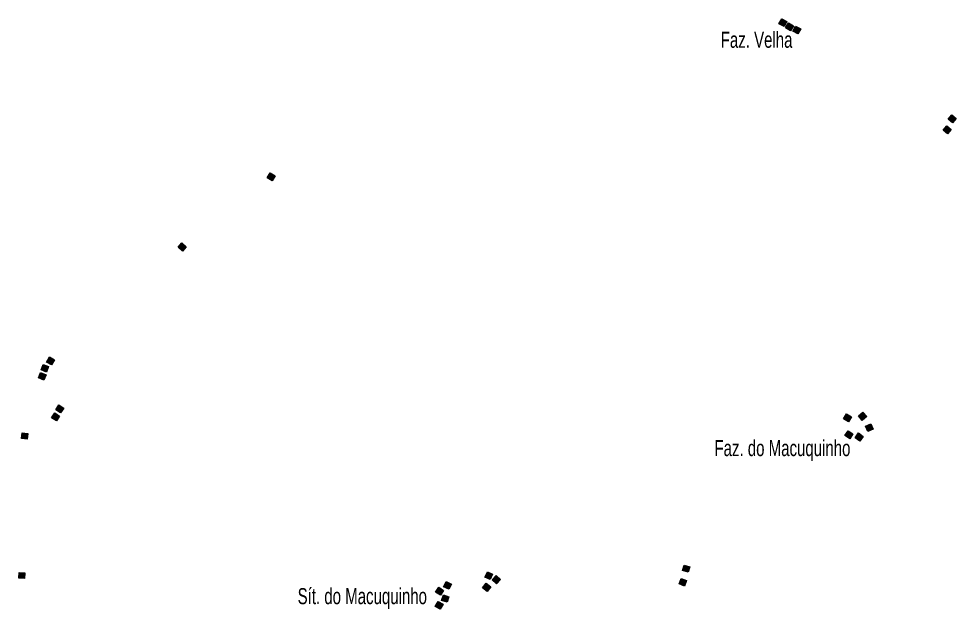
# Model space of a CAD drawing. Extents: x 679 to 705, y 7427.4 to 7455.4.
# Drawn here: x 688.118 to 692.796, y 7447.742 to 7450.688 of the extents above; entities that cross this region are included whole.
import ezdxf

# ---------------------------------------------------------------- set-up
doc = ezdxf.new("R2010")
doc.units = 0
doc.header["$LTSCALE"] = 0.032
doc.layers.add('2', color=7, linetype='Continuous', lineweight=25)
doc.layers.add('61', color=7, linetype='Continuous')

msp = doc.modelspace()

# ---------------------------------------------------------------- hatches: boundary and pattern name
at = {"layer": '2'}
for points in [[(691.9249, 7450.6883), (691.9505, 7450.6747), (691.937, 7450.6491), (691.9113, 7450.6627)], [(691.9831, 7450.6532), (691.9681, 7450.6284), (691.9433, 7450.6434), (691.9583, 7450.6682)], [(692.0196, 7450.6379), (692.0055, 7450.6126), (691.9801, 7450.6267), (691.9943, 7450.6521)], [(692.7735, 7450.2092), (692.7957, 7450.1905), (692.777, 7450.1683), (692.7548, 7450.187)], [(692.7708, 7450.1361), (692.7522, 7450.1138), (692.7299, 7450.1324), (692.7485, 7450.1547)], [(689.3721, 7449.9198), (689.3972, 7449.9053), (689.3827, 7449.8802), (689.3575, 7449.8947)], [(688.9321, 7449.5697), (688.9539, 7449.5507), (688.9349, 7449.5288), (688.913, 7449.5479)], [(688.2394, 7448.9629), (688.2665, 7448.9527), (688.2563, 7448.9256), (688.2292, 7448.9358)], [(688.271, 7449.0007), (688.2962, 7448.9863), (688.2817, 7448.9611), (688.2566, 7448.9756)], [(688.2272, 7448.9233), (688.254, 7448.9122), (688.2429, 7448.8854), (688.2161, 7448.8965)], [(688.3185, 7448.7617), (688.3426, 7448.7456), (688.3266, 7448.7215), (688.3024, 7448.7376)], [(692.3303, 7448.7253), (692.349, 7448.7031), (692.3268, 7448.6844), (692.3082, 7448.7066)], [(688.2973, 7448.7217), (688.3218, 7448.7062), (688.3063, 7448.6817), (688.2818, 7448.6972)], [(692.2474, 7448.7167), (692.2723, 7448.7018), (692.2575, 7448.6769), (692.2326, 7448.6918)], [(692.2561, 7448.6325), (692.2804, 7448.6166), (692.2646, 7448.5923), (692.2403, 7448.6082)], [(692.3688, 7448.667), (692.3811, 7448.6407), (692.3548, 7448.6284), (692.3425, 7448.6547)], [(688.1637, 7448.6196), (688.1606, 7448.5907), (688.1318, 7448.5938), (688.1349, 7448.6226)], [(692.3082, 7448.6215), (692.3316, 7448.6043), (692.3144, 7448.581), (692.2911, 7448.5981)], [(690.4825, 7447.9163), (690.4699, 7447.8902), (690.4438, 7447.9027), (690.4564, 7447.9289)], [(691.4663, 7447.9538), (691.4574, 7447.9262), (691.4298, 7447.9351), (691.4387, 7447.9627)], [(688.1485, 7447.9244), (688.147, 7447.8954), (688.118, 7447.897), (688.1195, 7447.9259)], [(690.5004, 7447.9099), (690.5212, 7447.8897), (690.5011, 7447.8688), (690.4802, 7447.889)], [(691.4236, 7447.8954), (691.4506, 7447.8848), (691.44, 7447.8578), (691.413, 7447.8684)], [(690.2376, 7447.8359), (690.222, 7447.8115), (690.1976, 7447.8271), (690.2132, 7447.8515)], [(690.2499, 7447.8798), (690.2764, 7447.8678), (690.2644, 7447.8414), (690.238, 7447.8534)], [(690.4509, 7447.8714), (690.4734, 7447.8531), (690.4551, 7447.8306), (690.4326, 7447.8489)], [(690.2372, 7447.8137), (690.2646, 7447.8041), (690.255, 7447.7767), (690.2276, 7447.7863)], [(690.2099, 7447.7814), (690.2353, 7447.7674), (690.2213, 7447.742), (690.1959, 7447.756)]]:
    msp.add_hatch(color=256, dxfattribs=at).paths.add_polyline_path(points)

# ---------------------------------------------------------------- linework, layer by layer
for points in [[(691.9249, 7450.6883), (691.9505, 7450.6747), (691.937, 7450.6491), (691.9113, 7450.6627)], [(691.9831, 7450.6532), (691.9681, 7450.6284), (691.9433, 7450.6434), (691.9583, 7450.6682)], [(692.0196, 7450.6379), (692.0055, 7450.6126), (691.9801, 7450.6267), (691.9943, 7450.6521)], [(692.7735, 7450.2092), (692.7957, 7450.1905), (692.777, 7450.1683), (692.7548, 7450.187)], [(692.7708, 7450.1361), (692.7522, 7450.1138), (692.7299, 7450.1324), (692.7485, 7450.1547)], [(689.3721, 7449.9198), (689.3972, 7449.9053), (689.3827, 7449.8802), (689.3575, 7449.8947)], [(688.9321, 7449.5697), (688.9539, 7449.5507), (688.9349, 7449.5288), (688.913, 7449.5479)], [(688.2394, 7448.9629), (688.2665, 7448.9527), (688.2563, 7448.9256), (688.2292, 7448.9358)], [(688.271, 7449.0007), (688.2962, 7448.9863), (688.2817, 7448.9611), (688.2566, 7448.9756)], [(688.2272, 7448.9233), (688.254, 7448.9122), (688.2429, 7448.8854), (688.2161, 7448.8965)], [(688.3185, 7448.7617), (688.3426, 7448.7456), (688.3266, 7448.7215), (688.3024, 7448.7376)], [(692.3303, 7448.7253), (692.349, 7448.7031), (692.3268, 7448.6844), (692.3082, 7448.7066)], [(688.2973, 7448.7217), (688.3218, 7448.7062), (688.3063, 7448.6817), (688.2818, 7448.6972)], [(692.2474, 7448.7167), (692.2723, 7448.7018), (692.2575, 7448.6769), (692.2326, 7448.6918)], [(692.2561, 7448.6325), (692.2804, 7448.6166), (692.2646, 7448.5923), (692.2403, 7448.6082)], [(692.3688, 7448.667), (692.3811, 7448.6407), (692.3548, 7448.6284), (692.3425, 7448.6547)], [(688.1637, 7448.6196), (688.1606, 7448.5907), (688.1318, 7448.5938), (688.1349, 7448.6226)], [(692.3082, 7448.6215), (692.3316, 7448.6043), (692.3144, 7448.581), (692.2911, 7448.5981)], [(690.4825, 7447.9163), (690.4699, 7447.8902), (690.4438, 7447.9027), (690.4564, 7447.9289)], [(691.4663, 7447.9538), (691.4574, 7447.9262), (691.4298, 7447.9351), (691.4387, 7447.9627)], [(688.1485, 7447.9244), (688.147, 7447.8954), (688.118, 7447.897), (688.1195, 7447.9259)], [(690.5004, 7447.9099), (690.5212, 7447.8897), (690.5011, 7447.8688), (690.4802, 7447.889)], [(691.4236, 7447.8954), (691.4506, 7447.8848), (691.44, 7447.8578), (691.413, 7447.8684)], [(690.2376, 7447.8359), (690.222, 7447.8115), (690.1976, 7447.8271), (690.2132, 7447.8515)], [(690.2499, 7447.8798), (690.2764, 7447.8678), (690.2644, 7447.8414), (690.238, 7447.8534)], [(690.4509, 7447.8714), (690.4734, 7447.8531), (690.4551, 7447.8306), (690.4326, 7447.8489)], [(690.2372, 7447.8137), (690.2646, 7447.8041), (690.255, 7447.7767), (690.2276, 7447.7863)], [(690.2099, 7447.7814), (690.2353, 7447.7674), (690.2213, 7447.742), (690.1959, 7447.756)]]:
    msp.add_lwpolyline(points, close=True, dxfattribs=at)

# ---------------------------------------------------------------- texts
at = {"layer": '61', "width": 0.7}
for s, p in [('Faz. Velha', (691.6206, 7450.5434)), ('Faz. do Macuquinho', (691.5892, 7448.5061)), ('Sít. do Macuquinho', (689.5095, 7447.7674))]:
    msp.add_text(s, height=0.08, dxfattribs=at).set_placement(p)

doc.saveas('drawing.dxf')
